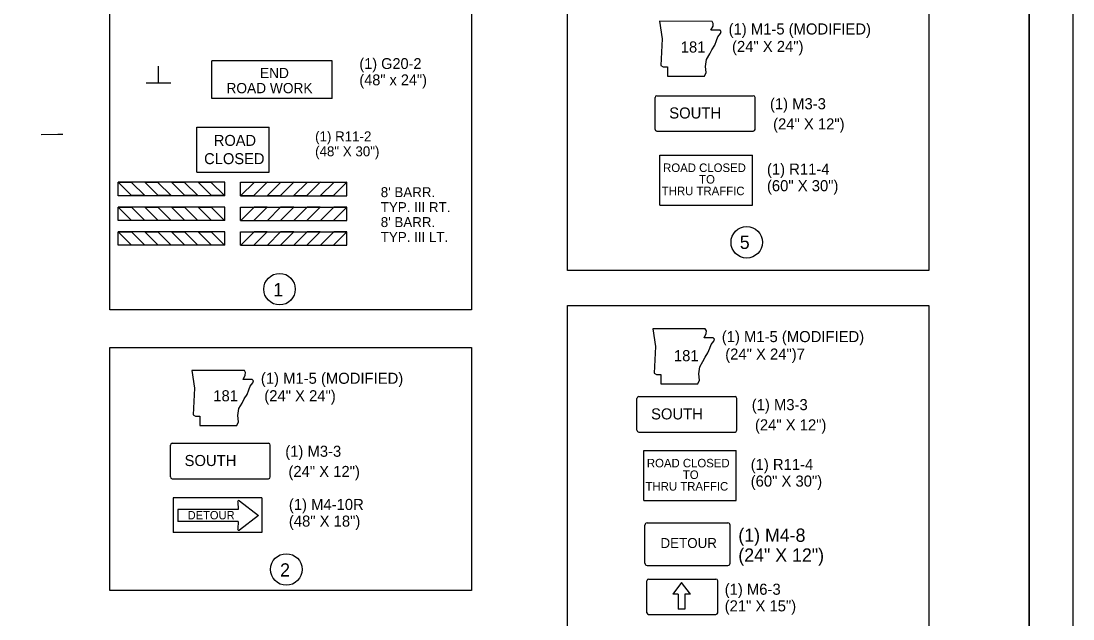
# Model space of a CAD drawing. Extents: x 9792 to 14027, y 9583 to 10649.
# Drawn here: x 10889 to 11459, y 10064 to 10387 of the extents above; entities that cross this region are included whole.
import ezdxf

# ---------------------------------------------------------------- set-up
doc = ezdxf.new("R2010")
doc.units = 0
for name, color, linetype in [('Default', 7, 'Continuous'), ('R_Border', 7, 'Continuous'), ('R_Border Notes', 7, 'Continuous'), ('R_MOT', 7, 'Continuous'), ('R_No Plot', 7, 'Continuous')]:
    doc.layers.add(name, color=color, linetype=linetype)

msp = doc.modelspace()

# ---------------------------------------------------------------- linework, layer by layer
at = {"layer": 'Default'}
for p, q in [((11057.6, 10365.88), (10992.5, 10365.88)), ((10992.5, 10345.42), (10992.5, 10365.88)), ((11057.6, 10345.42), (11057.6, 10365.88)), ((10963.62, 10353.98), (10963.58, 10363.01)), ((10970.21, 10353.82), (10956.97, 10353.76)), ((11057.6, 10345.42), (10992.5, 10345.42))]:
    msp.add_line(p, q, dxfattribs=at)
msp.add_lwpolyline([(10911.74, 10326.01), (10910.45, 10325.96), (10909.07, 10325.9), (10900.02, 10325.81)], dxfattribs=at)
at = {"layer": 'R_Border'}
msp.add_line((11435.16, 9602.55), (11435.16, 10629.85), dxfattribs=at)
at = {"layer": 'R_Border Notes'}
for p, q in [((11232.6, 10328.72), (11232.6, 10346)), ((11233.55, 10346.96), (11285.73, 10346.96)), ((11286.69, 10328.72), (11286.69, 10346)), ((11233.55, 10327.76), (11285.73, 10327.76)), ((11235.19, 10314.82), (11285.38, 10314.82)), ((11235.19, 10287.67), (11235.19, 10314.82)), ((11285.38, 10287.67), (11285.38, 10314.82)), ((11235.19, 10287.67), (11285.38, 10287.67)), ((11222.75, 10165.7), (11222.75, 10182.98)), ((11223.71, 10183.94), (11275.88, 10183.94)), ((11276.84, 10165.7), (11276.84, 10182.98)), ((11223.71, 10164.74), (11275.88, 10164.74)), ((10970.04, 10140.45), (10970.04, 10157.73)), ((10971, 10158.69), (11023.18, 10158.69)), ((11024.14, 10140.45), (11024.14, 10157.73)), ((11226.38, 10154.8), (11276.57, 10154.8)), ((11226.38, 10127.66), (11226.38, 10154.8)), ((11276.57, 10127.66), (11276.57, 10154.8)), ((10971, 10139.49), (11023.18, 10139.49)), ((11226.38, 10127.66), (11276.57, 10127.66)), ((11228.11, 10066.91), (11228.11, 10084.19)), ((11229.07, 10085.15), (11265.56, 10085.15)), ((11246.91, 10083.19), (11242.11, 10076.95)), ((11251.71, 10076.95), (11246.91, 10083.19)), ((11266.52, 10066.91), (11266.52, 10084.19)), ((11245.11, 10076.95), (11242.11, 10076.95)), ((11245.11, 10076.95), (11245.11, 10073.14)), ((11251.71, 10076.95), (11248.71, 10076.95)), ((11248.71, 10076.95), (11248.71, 10073.14)), ((11245.11, 10073.14), (11245.11, 10068.77)), ((11248.71, 10068.77), (11245.11, 10068.77)), ((11248.71, 10073.14), (11248.71, 10068.77)), ((11229.07, 10065.95), (11265.56, 10065.95))]:
    msp.add_line(p, q, dxfattribs=at)
for points in [[(10937.26, 10466.18), (11133.09, 10466.18), (11133.09, 10231.02), (10937.26, 10231.02)], [(11185.08, 10402.65), (11380.91, 10402.65), (11380.91, 10252.35), (11185.08, 10252.35)], [(11234.97, 10387.29), (11236.39, 10377.79), (11235.74, 10363.38), (11237, 10362.59), (11239.37, 10362.59), (11239.37, 10357.52), (11259.32, 10357.5), (11260.28, 10359.56), (11259.96, 10362.88), (11260.44, 10366.68), (11262.19, 10369.69), (11263.3, 10371.91), (11264.88, 10374.28), (11265.84, 10376.81), (11266.63, 10378.87), (11268.06, 10380.61), (11268.38, 10381.72), (11267.74, 10382.51), (11262.83, 10382.51), (11263.94, 10384.73), (11264.1, 10386.16), (11263.45, 10387.25)], [(11185.08, 10233.35), (11380.91, 10233.35), (11380.91, 10042.2), (11185.08, 10042.2)], [(11231.28, 10220.65), (11232.7, 10211.15), (11232.05, 10196.74), (11233.31, 10195.95), (11235.69, 10195.95), (11235.69, 10190.87), (11255.64, 10190.85), (11256.59, 10192.91), (11256.27, 10196.24), (11256.75, 10200.04), (11258.5, 10203.05), (11259.61, 10205.26), (11261.2, 10207.63), (11262.15, 10210.17), (11262.94, 10212.23), (11264.37, 10213.97), (11264.69, 10215.07), (11264.05, 10215.86), (11259.14, 10215.87), (11260.25, 10218.08), (11260.42, 10219.51), (11259.76, 10220.61)], [(10937.26, 10210.65), (11133.09, 10210.65), (11133.09, 10078.87), (10937.26, 10078.87)], [(10981.6, 10198.07), (10983.02, 10188.57), (10982.37, 10174.16), (10983.63, 10173.37), (10986, 10173.37), (10986, 10168.3), (11005.95, 10168.28), (11006.91, 10170.34), (11006.59, 10173.66), (11007.07, 10177.46), (11008.82, 10180.47), (11009.93, 10182.68), (11011.51, 10185.06), (11012.47, 10187.59), (11013.26, 10189.65), (11014.69, 10191.39), (11015.01, 10192.49), (11014.37, 10193.29), (11009.46, 10193.29), (11010.57, 10195.51), (11010.73, 10196.94), (11010.08, 10198.03)]]:
    msp.add_lwpolyline(points, close=True, dxfattribs=at)
for centre in [(11282.24, 10267.6), (11029.13, 10242.17), (11032.81, 10090.32)]:
    msp.add_circle(centre, 8.55, dxfattribs=at)
for centre, start, end in [((11233.55, 10346), 90, 180), ((11285.73, 10346), 0, 90), ((11233.55, 10328.72), 180, 270), ((11285.73, 10328.72), 270, 0), ((11223.71, 10182.98), 90, 180), ((11275.88, 10182.98), 0, 90), ((11223.71, 10165.7), 180, 270), ((11275.88, 10165.7), 270, 0), ((10971, 10157.73), 90, 180), ((11023.18, 10157.73), 0, 90), ((10971, 10140.45), 180, 270), ((11023.18, 10140.45), 270, 0), ((11229.07, 10084.19), 90, 180), ((11265.56, 10084.19), 0, 90), ((11229.07, 10066.91), 180, 270), ((11265.56, 10066.91), 270, 0)]:
    msp.add_arc(centre, 0.96, start, end, dxfattribs=at)
at = {"layer": 'R_MOT'}
for p, q in [((10984.35, 10305.49), (10984.35, 10329.92)), ((10984.35, 10329.92), (11023.45, 10329.92)), ((11023.45, 10305.49), (11023.45, 10329.92)), ((10984.35, 10305.49), (11023.45, 10305.49)), ((10999.43, 10300.05), (10941.8, 10300.05)), ((10941.8, 10292.82), (10941.8, 10300.05)), ((10999.43, 10292.82), (10999.43, 10300.05)), ((11007.98, 10300.05), (11065.6, 10300.05)), ((11007.98, 10292.82), (11007.98, 10300.05)), ((11065.6, 10292.82), (11065.6, 10300.05)), ((10941.84, 10292.84), (10941.8, 10292.88)), ((10999.43, 10292.82), (10941.8, 10292.82)), ((11007.98, 10292.82), (11065.6, 10292.82)), ((11065.56, 10292.84), (11065.6, 10292.88)), ((10999.43, 10286.64), (10941.8, 10286.64)), ((10941.8, 10279.43), (10941.8, 10286.64)), ((10941.8, 10279.43), (10941.8, 10286.64)), ((10999.43, 10279.43), (10999.43, 10286.64)), ((11007.98, 10286.64), (11065.6, 10286.64)), ((11007.98, 10279.43), (11007.98, 10286.64)), ((11065.6, 10279.43), (11065.6, 10286.64)), ((11065.6, 10279.43), (11065.6, 10286.64)), ((10999.43, 10279.43), (10941.8, 10279.43)), ((11007.98, 10279.43), (11065.6, 10279.43)), ((10999.43, 10273.27), (10941.8, 10273.27)), ((10941.8, 10266.06), (10941.8, 10273.27)), ((10999.43, 10266.06), (10999.43, 10273.27)), ((11007.98, 10273.27), (11065.6, 10273.27)), ((11007.98, 10266.06), (11007.98, 10273.27)), ((11065.6, 10266.06), (11065.6, 10273.27)), ((10999.43, 10266.06), (10941.8, 10266.06)), ((11007.98, 10266.06), (11065.6, 10266.06)), ((11019.63, 10129.08), (10971.55, 10129.08)), ((10971.55, 10129.08), (10971.55, 10110.39)), ((11006.46, 10126.9), (11006.78, 10122.89)), ((11007.52, 10127.48), (11017.76, 10119.58)), ((11019.63, 10129.08), (11019.63, 10110.39)), ((11006.78, 10122.89), (10973.97, 10122.89)), ((10973.97, 10122.89), (10973.97, 10116.28)), ((11006.78, 10116.28), (10973.97, 10116.28)), ((11006.78, 10116.28), (11006.46, 10112.27)), ((11017.76, 10119.58), (11007.52, 10111.69)), ((11227.07, 10093.66), (11227.07, 10114.4)), ((11228.22, 10115.55), (11272, 10115.55)), ((11273.15, 10093.66), (11273.15, 10114.4)), ((11019.63, 10110.39), (10971.55, 10110.39)), ((11228.22, 10092.51), (11272, 10092.51))]:
    msp.add_line(p, q, dxfattribs=at)
for points in [[(10941.8, 10300.05), (10948.88, 10300.03), (10956.08, 10292.84), (10949.01, 10292.84)], [(10956.2, 10300.05), (10963.28, 10300.03), (10970.48, 10292.84), (10963.41, 10292.84)], [(10970.6, 10300.05), (10977.68, 10300.03), (10984.88, 10292.84), (10977.81, 10292.84)], [(10985, 10300.05), (10992.08, 10300.03), (10999.28, 10292.84), (10992.21, 10292.84)], [(11022.4, 10300.05), (11015.32, 10300.03), (11008.13, 10292.84), (11015.19, 10292.84)], [(11036.8, 10300.05), (11029.72, 10300.03), (11022.53, 10292.84), (11029.59, 10292.84)], [(11051.2, 10300.05), (11044.12, 10300.03), (11036.93, 10292.84), (11043.99, 10292.84)], [(11065.6, 10300.05), (11058.52, 10300.03), (11051.33, 10292.84), (11058.39, 10292.84)], [(10941.8, 10286.64), (10948.88, 10286.62), (10956.08, 10279.43), (10949.01, 10279.43)], [(10956.2, 10286.64), (10963.28, 10286.62), (10970.48, 10279.43), (10963.41, 10279.43)], [(10970.6, 10286.64), (10977.68, 10286.62), (10984.88, 10279.43), (10977.81, 10279.43)], [(10985, 10286.64), (10992.08, 10286.62), (10999.28, 10279.43), (10992.21, 10279.43)], [(11022.4, 10286.64), (11015.32, 10286.62), (11008.13, 10279.43), (11015.19, 10279.43)], [(11036.8, 10286.64), (11029.72, 10286.62), (11022.53, 10279.43), (11029.59, 10279.43)], [(11051.2, 10286.64), (11044.12, 10286.62), (11036.93, 10279.43), (11043.99, 10279.43)], [(11065.6, 10286.64), (11058.52, 10286.62), (11051.33, 10279.43), (11058.39, 10279.43)], [(10941.8, 10273.27), (10948.88, 10273.25), (10956.08, 10266.06), (10949.01, 10266.06)], [(10956.2, 10273.27), (10963.28, 10273.25), (10970.48, 10266.06), (10963.41, 10266.06)], [(10970.6, 10273.27), (10977.68, 10273.25), (10984.88, 10266.06), (10977.81, 10266.06)], [(10985, 10273.27), (10992.08, 10273.25), (10999.28, 10266.06), (10992.21, 10266.06)], [(11022.4, 10273.27), (11015.32, 10273.25), (11008.13, 10266.06), (11015.19, 10266.06)], [(11036.8, 10273.27), (11029.72, 10273.25), (11022.53, 10266.06), (11029.59, 10266.06)], [(11051.2, 10273.27), (11044.12, 10273.25), (11036.93, 10266.06), (11043.99, 10266.06)], [(11065.6, 10273.27), (11058.52, 10273.25), (11051.33, 10266.06), (11058.39, 10266.06)]]:
    msp.add_lwpolyline(points, close=True, dxfattribs=at)
for centre, radius, start, end in [((11007.11, 10126.95), 0.66, 52.3853, 184.5739), ((11228.22, 10114.4), 1.15, 90, 180), ((11272, 10114.4), 1.15, 0, 90), ((11007.11, 10112.22), 0.66, 175.4261, 307.6112), ((11228.22, 10093.66), 1.15, 180, 270), ((11272, 10093.66), 1.15, 270, 0)]:
    msp.add_arc(centre, radius, start, end, dxfattribs=at)
at = {"layer": 'R_No Plot'}
for points in [[(9792.23, 10649.32), (11458.93, 10649.32), (11458.93, 9582.63), (9792.23, 9582.63)], [(11023.86, 10629.85), (11023.86, 10580.45), (11202.52, 10580.45), (11202.52, 10565.85), (11318.52, 10565.85), (11318.52, 10444.19), (11435.16, 10444.19), (11435.16, 9602.55), (9854.26, 9602.55), (9854.26, 10629.85)]]:
    msp.add_lwpolyline(points, close=True, dxfattribs=at)

# ---------------------------------------------------------------- texts
at = {"layer": 'Default'}
for s, height, p in [('(1) G20-2', 5.881, (11072.38, 10361.44)), ('END', 5.557, (11018.52, 10356.52)), ('ROAD WORK', 5.557, (11000.38, 10348.31)), ('(48" x 24")', 5.88, (11072.38, 10352.62))]:
    msp.add_text(s, height=height, rotation=360, dxfattribs=at).set_placement(p)
at = {"layer": 'R_Border Notes'}
for s, height, p in [('(1) M1-5 (MODIFIED)', 6, (11272.39, 10380.13)), ('181', 6, (11246.46, 10370.37)), ('(24" X 24")', 6.0005, (11274.25, 10370.66)), ('(1) M3-3', 6, (11294.78, 10339.63)), ('  SOUTH', 6, (11235.78, 10334.62)), ('(24" X 12")', 6, (11296.5, 10328.69)), ('ROAD CLOSED', 4.604, (11236.92, 10305.65)), ('(1) R11-4', 6, (11293.17, 10304.23)), ('TO', 4.604, (11256.43, 10299.37)), ('THRU TRAFFIC', 4.604, (11236.2, 10293.09)), ('(60" X 30")', 6, (11293.17, 10295.23)), ('5', 7.2, (11278.43, 10263.95)), ('1', 7.2, (11025.77, 10238.32)), ('(1) M1-5 (MODIFIED)', 6, (11268.7, 10213.48)), ('181', 6, (11242.77, 10203.15)), ('(24" X 24")7', 6.0005, (11270.56, 10204.02)), ('(1) M1-5 (MODIFIED)', 6, (11019.02, 10190.9)), ('181', 6, (10993.24, 10181.42)), ('(24" X 24")', 6.0005, (11020.88, 10181.44)), ('(1) M3-3', 6, (11284.93, 10176.62)), ('  SOUTH', 6, (11225.93, 10171.6)), ('(24" X 12")', 6, (11286.66, 10165.67)), ('(1) M3-3', 6, (11032.23, 10151.36)), ('  SOUTH', 6, (10973.23, 10146.35)), ('ROAD CLOSED', 4.604, (11228.12, 10145.64)), ('(1) R11-4', 6, (11284.36, 10144.21)), ('(24" X 12")', 6, (11033.95, 10140.42)), ('TO', 4.604, (11247.62, 10139.35)), ('THRU TRAFFIC', 4.604, (11227.39, 10133.07)), ('(60" X 30")', 6, (11284.36, 10135.21)), ('2', 7.2, (11029.45, 10086.47)), ('(1) M6-3', 6.001, (11270.27, 10076.61)), ('(21" X 15")', 6.0007, (11270.27, 10067.61))]:
    msp.add_text(s, height=height, dxfattribs=at).set_placement(p)
at = {"layer": 'R_MOT'}
for s, height, p in [('ROAD', 5.919, (10993.55, 10319.81)), ('(1) R11-2', 5.4, (11048.4, 10322.26)), ('(48" X 30")', 5.4, (11048.4, 10314.16)), ('CLOSED', 5.949, (10988.29, 10309.9)), ("8' BARR.", 5.4, (11083.97, 10292.02)), ('TYP. III RT.', 5.4, (11083.97, 10283.92)), ("8' BARR.", 5.4, (11083.97, 10275.82)), ('TYP. III LT.', 5.4, (11083.97, 10267.72)), ('(1) M4-8', 7.2, (11277.65, 10105.3)), ('DETOUR', 5.413, (11235.49, 10101.94)), ('(24" X 12")', 7.2, (11277.65, 10094.5))]:
    msp.add_text(s, height=height, dxfattribs=at).set_placement(p)
for s, height, p in [('(1) M4-10R', 6, (11034.19, 10122.53)), ('DETOUR', 4.511, (10979.34, 10117.48)), ('(48" X 18")', 6, (11034.19, 10113.53))]:
    msp.add_text(s, height=height, rotation=360, dxfattribs=at).set_placement(p)

doc.saveas('drawing.dxf')
